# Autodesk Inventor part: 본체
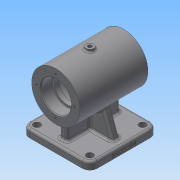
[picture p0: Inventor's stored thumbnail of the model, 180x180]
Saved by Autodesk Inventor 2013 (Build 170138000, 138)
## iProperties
Created: 2019-06
Part Number: 본체
Material: 일반
Document SubType Name: Modeling
Designer: Administrator
Density: 1 g/cm^3
Author: Administrator
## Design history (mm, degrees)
sketch "스케치1"
  geometry: C1 r 32 at (0, 0); 1 further point
  constraints: 1 centre point, 1 coincident
  dimensions: "d0" = 64 diameter of C1
extrude "돌출1" new body sketch "스케치1" stored distance "d1" = 90; taper "d2" = 0 deg
sketch "스케치2"
  geometry: C1 r 32 at (0, 0) reference; C2 r 20 at (0, 0)
  constraints: 1 centre point, 1 coincident
  dimensions: "d3" = 40 diameter of C2
extrude "돌출2" cut sketch "스케치2" distance "d4" = 15; taper "d5" = 0 deg
sketch "스케치4"
  geometry: C1 r 20 at (0, 0) reference; C2 r 17 at (0, 0)
  constraints: 1 centre point, 1 coincident
  dimensions: "d9" = 34 diameter of C2
extrude "돌출4" cut sketch "스케치4" distance "d10" = 6; taper "d11" = 0 deg
sketch "스케치5"
  geometry: C1 r 17 at (0, 0) reference; C2 r 25 at (0, 0)
  constraints: 1 centre point, 1 coincident
  dimensions: "d12" = 50 diameter of C2
extrude "돌출5" cut sketch "스케치5" distance "d13" = 48; taper "d14" = 0 deg
fillet "모깎기1" dims "d15" = 0.6
fillet "모깎기2" dims "d16" = 3
chamfer "모따기1" distance "d17" = 1; stored, may be unused: second distance "d18" = 2, angle "d19" = 45 deg
node "작업 평면1"
sketch "스케치6"
  geometry: L1 (-45, 45)-(45, 45); L2 (45, 45)-(45, -45); L3 (45, -45)-(-45, -45); L4 (-45, -45)-(-45, 45); L5 (-45, 45)-(45, -45); L6 (45, 45)-(-45, -45); 1 further point
  constraints: 12 end point, 2 midpoint, 2 parallel, 1 horizontal, 1 perpendicular
  dimensions: "d21" = 90 distance of L2.end L3.end; "d22" = 90 distance of L1.end L2.end
extrude "돌출6" join sketch "스케치6" distance "d23" = 10; taper "d24" = 0 deg
fillet "모깎기3" dims "d25" = 10
sketch "스케치7"
  geometry: L1 (-5, -35)-(5, -35); L2 (5, -35)-(5, 35); L3 (5, 35)-(-5, 35); L4 (-5, 35)-(-5, -35); L5 (-5, -35)-(5, 35); L6 (5, -35)-(-5, 35); 1 further point
  constraints: 12 end point, 2 midpoint, 2 parallel, 1 horizontal, 1 perpendicular
  dimensions: "d26" = 10 distance of L3.end L2.end; "d27" = 70 distance of L2.end L1.end
extrude "돌출7" join sketch "스케치7" stored distance "d28" = 10; taper "d29" = 0 deg
sketch "스케치8"
  geometry: L1 (45, -65)-(-45, -65) reference; L2 (-45, -65)-(-45, -55) reference; L3 (-45, -55)-(-5, -55) reference; L4 (-5, -55)-(-5, -31.607) reference; L5 (5, -31.607)-(5, -55) reference; L6 (5, -55)-(45, -55) reference; L7 (45, -55)-(45, -65) reference; L8 (35, -55)-(29.005, -38.529); L9 (35, -55)-(52.528, -55); C1 r 25 at (0, 0) reference; A1 r 32 centre (0, 0) between (5, -31.607) and (-5, -31.607) reference; 1 further point
  constraints: 4 end point, 1 equal length, 1 horizontal, 1 point on line
  dimensions: "d30" = 110 deg angle of L9 L8; "d31" = 10 distance of L6.end L8.start
feature "리브1" sketch "스케치8" dims "d32" = 1, "d33" = 10, "d34" = 0, "d35" = 0, "d36" = 1, "d37" = 1
node "작업 평면2"
sketch "스케치9"
  geometry: C1 r 5 at (0, 0); 1 further point
  constraints: 1 centre point, 1 coincident
  dimensions: "d39" = 10 diameter of C1
extrude "돌출8" join sketch "스케치9" stored distance "d40" = 10; taper "d41" = 0 deg
fillet "모깎기4" dims "d42" = 2
hole "구멍1" diameter "d45" = 4.917; stored, may be unused: countersink angle "d49" = 90 deg, drill point angle "d51" = 118 deg; dims "d43" = 10, "d44" = 10, "d46" = 6, "d47" = 4, "d48" = 2, "d50" = 8
sketch "스케치10"
  geometry: C1 r 32 at (0, 0) reference; 1 further point
  constraints: 1 vertical alignment
  dimensions: "d52" = 25 distance of C1.centre point (0, 25)
hole "구멍2" sketch "스케치10" at (0, 25) diameter "d53" = 3.242; stored, may be unused: countersink angle "d57" = 90 deg, drill point angle "d59" = 118 deg; dims "d54" = 7, "d55" = 4, "d56" = 2, "d58" = 9
sketch "스케치11"
  geometry: A1 r 10 centre (35, 35) between (45, 35) and (35, 45) reference; A2 r 10 centre (-35, 35) between (-35, 45) and (-45, 35) reference; A3 r 10 centre (-35, -35) between (-45, -35) and (-35, -45) reference; A4 r 10 centre (35, -35) between (35, -45) and (45, -35) reference; 5 further points
  constraints: 4 coincident
hole "구멍3" sketch "스케치11" at (-35, 35), (-35, -35), (35, -35), (35, 35) diameter "d63" = 9; stored, may be unused: countersink angle "d67" = 90 deg, drill point angle "d69" = 118 deg; dims "d64" = 7, "d65" = 4, "d66" = 2, "d68" = 9
sketch "스케치12"
  geometry: L1 (45, -35)-(45, 35) reference; L2 (35, 45)-(-35, 45) reference; L3 (-45, 35)-(-45, -35) reference; L4 (-35, -45)-(35, -45) reference; L5 (-26.34, 40)-(26.34, 40); L6 (40, 26.34)-(40, -26.34); L7 (26.34, -40)-(-26.34, -40); L8 (-40, -26.34)-(-40, 26.34); L9 (-40, 40)-(40, -40); L10 (40, 40)-(-40, -40); C1 r 4.5 at (35, 35) reference; A1 r 10 centre (35, 35) between (45, 35) and (35, 45) reference; A2 r 10 centre (-35, 35) between (-35, 45) and (-45, 35) reference; A3 r 10 centre (-35, -35) between (-45, -35) and (-35, -45) reference; A4 r 10 centre (35, -35) between (35, -45) and (45, -35) reference; A5 r 10 centre (-35, 35) between (-40, 26.34) and (-26.34, 40); A6 r 10 centre (-35, -35) between (-26.34, -40) and (-40, -26.34); A7 r 10 centre (35, -35) between (40, -26.34) and (26.34, -40); A8 r 10 centre (35, 35) between (26.34, 40) and (40, 26.34); 1 further point
  constraints: 16 end point, 8 point on circle, 4 centre point, 4 coincident, 4 concentric, 2 midpoint, 2 parallel, 1 horizontal, 1 perpendicular
  dimensions: "d70" = 80 distance of L9.end L10.end; "d71" = 80 distance of L10.start L9.end; "d72" = 10 radius of A8; "d75" = 5 distance between parallel lines of L5 L2; "d76" = 5 distance between parallel lines of L3 L8; "d77" = 5 distance between parallel lines of L4 L7; "d78" = 5 distance between parallel lines of L1 L6
extrude "돌출9" cut sketch "스케치12" distance "d79" = 5; taper "d80" = 0 deg
fillet "모깎기5" dims "d81" = 3
fillet "모깎기6" dims "d82" = 3
fillet "모깎기7" dims "d83" = 3
sketch "스케치13"
  geometry: L1 (-10, 7)-(-10, 0) reference; L2 (0, 0)-(-10, 0) reference; 2 further points
  constraints: 1 other
  dimensions: "d84" = 45 distance from line of point (35, 4) L1; "d85" = 4 distance from line of point (35, 4) L2
feature "엠보싱1" sketch "스케치13" dims "d14" = 0, "d86" = 0.5, "d87" = 0
node "솔리드1"
mirror "대칭2"
mirror "대칭3"
pattern_circular "원형 패턴1" dims angle "d61" = 360 deg
mirror "대칭4"
node "절단 모서리 투영1"
other parameters: "d20" = -65
